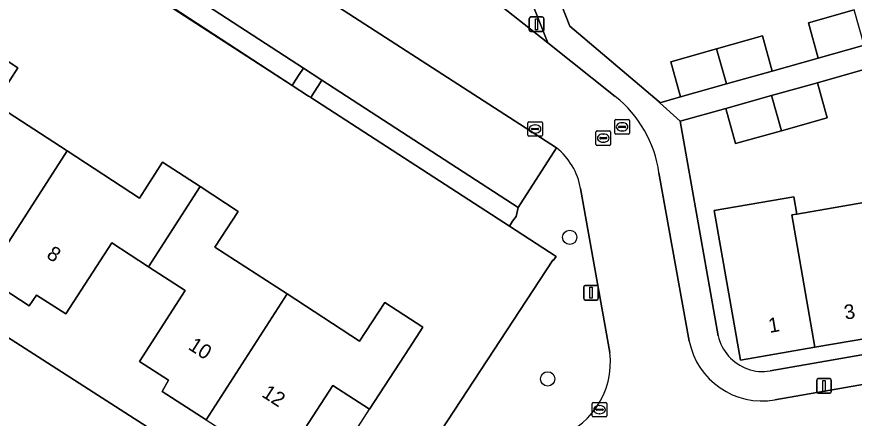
# Model space of a CAD drawing. Extents: x 160157 to 160921, y 381516 to 382045.
# Drawn here: x 160391 to 160448.3, y 381586.3 to 381613.8 of the extents above; entities that cross this region are included whole.
import ezdxf

# ---------------------------------------------------------------- set-up
doc = ezdxf.new("R2010")
doc.units = 0
for name, color, linetype in [('IMGEO_Berm_groen', 7, 'Continuous'), ('IMGEO_Boom', 7, 'Continuous'), ('IMGEO_Erf', 7, 'Continuous'), ('IMGEO_Groenvoorziening', 7, 'Continuous'), ('IMGEO_Haag', 7, 'Continuous'), ('IMGEO_Hek', 7, 'Continuous'), ('IMGEO_Kolk', 7, 'Continuous'), ('IMGEO_Lichtmast', 7, 'Continuous'), ('IMGEO_Muur', 7, 'Continuous'), ('IMGEO_Pand', 7, 'Continuous'), ('IMGEO_Pand_nummerreeks', 7, 'Continuous'), ('IMGEO_Pand_overbouw', 7, 'Continuous'), ('IMGEO_Parkeervlak_open', 7, 'Continuous'), ('IMGEO_Rijbaan_lokaal_open', 7, 'Continuous'), ('IMGEO_Rioolput', 7, 'Continuous'), ('IMGEO_Voetpad_open', 7, 'Continuous')]:
    doc.layers.add(name, color=color, linetype=linetype)

msp = doc.modelspace()

# ---------------------------------------------------------------- linework, layer by layer
at = {"layer": 'IMGEO_Berm_groen'}
msp.add_lwpolyline([(160423.335, 381615.167), (160427.338, 381611.987), (160422.807, 381623.418)], dxfattribs=at)
at = {"layer": 'IMGEO_Boom'}
for centre in [(160428.832, 381598.68), (160427.323, 381588.986)]:
    msp.add_circle(centre, 0.489, dxfattribs=at)
at = {"layer": 'IMGEO_Erf'}
for points in [[(160319.436, 381635.145), (160331.317, 381627.79), (160361.156, 381608.556), (160362.318, 381609.828), (160405.188, 381582.297), (160414.171, 381576.508), (160427.676, 381597.123), (160427.729, 381597.121), (160427.898, 381597.365), (160424.706, 381599.434), (160411.1, 381608.252), (160410.955, 381608.346), (160409.818, 381609.084), (160392.312, 381620.441), (160387.378, 381623.641), (160380.613, 381628.03), (160378.993, 381629.081)], [(160425.558, 381623.211), (160425.011, 381622.871), (160428.842, 381613.142), (160434.955, 381607.95), (160435.012, 381607.897), (160436.424, 381608.295), (160435.754, 381610.698), (160438.887, 381611.582), (160442.019, 381612.466), (160442.69, 381610.06), (160445.85, 381610.95), (160445.18, 381613.358), (160448.313, 381614.243)], [(160388.457, 381611.96), (160391.045, 381610.273), (160389.452, 381607.827), (160394.423, 381604.59), (160399.366, 381601.371), (160400.96, 381603.819), (160403.526, 381602.148), (160406.131, 381600.452), (160404.544, 381598.015), (160409.48, 381594.8), (160414.449, 381591.564), (160416.176, 381594.217), (160418.776, 381592.526), (160417.859, 381591.116), (160415.133, 381586.924), (160412.612, 381588.544), (160410.42, 381585.162)], [(160449.386, 381610.274), (160445.787, 381609.263), (160446.456, 381606.859), (160443.323, 381605.977), (160440.19, 381605.095), (160439.52, 381607.504), (160436.387, 381606.629), (160438.993, 381591.936)], [(160450.722, 381592.036), (160445.619, 381591.148), (160440.515, 381590.26), (160438.723, 381600.521), (160444.179, 381601.45), (160444.381, 381600.268), (160448.976, 381601.06)], [(160403.937, 381586.18), (160400.921, 381588.125), (160401.367, 381588.9), (160399.374, 381590.172), (160402.506, 381595.039), (160399.991, 381596.666), (160397.476, 381598.293), (160394.328, 381593.43), (160392.318, 381594.717), (160391.826, 381593.98), (160388.821, 381595.924)], [(160442.549, 381589.545), (160466.211, 381593.679)]]:
    msp.add_lwpolyline(points, dxfattribs=at)
for centre, radius, start, end in [((160442.05, 381592.631), 3.135, 192.81425, 250.63181), ((160442.01, 381592.362), 2.868, 249.59106, 280.8262)]:
    msp.add_arc(centre, radius, start, end, dxfattribs=at)
at = {"layer": 'IMGEO_Groenvoorziening'}
for points in [[(160400.97, 381616.489), (160393.122, 381621.564), (160392.872, 381621.233), (160392.567, 381620.809), (160392.312, 381620.441), (160409.818, 381609.084), (160410.056, 381609.447), (160410.307, 381609.829), (160410.593, 381610.266), (160404.025, 381614.525)], [(160411.859, 381609.445), (160411.575, 381608.999), (160411.332, 381608.617), (160411.1, 381608.252), (160424.706, 381599.434), (160424.916, 381599.792), (160425.159, 381600.114), (160425.31, 381600.723)]]:
    msp.add_lwpolyline(points, close=True, dxfattribs=at)
for points in [[(160427.931, 381604.811), (160425.31, 381600.723), (160425.159, 381600.114), (160424.916, 381599.792), (160424.706, 381599.434), (160427.898, 381597.365), (160427.729, 381597.121), (160427.676, 381597.123), (160414.171, 381576.508), (160414.766, 381576.125), (160418.106, 381581.208)], [(160431.572, 381590.8), (160429.575, 381602.028)]]:
    msp.add_lwpolyline(points, dxfattribs=at)
for centre, radius, start, end in [((160425.017, 381601.213), 4.63, 10.14305, 51.00015), ((160426.158, 381590.124), 5.456, 284.32458, 7.11479)]:
    msp.add_arc(centre, radius, start, end, dxfattribs=at)
at = {"layer": 'IMGEO_Haag'}
for points in [[(160392.872, 381621.233), (160392.567, 381620.809), (160392.312, 381620.441), (160409.818, 381609.084), (160410.056, 381609.447), (160410.307, 381609.829), (160410.593, 381610.266), (160404.025, 381614.525), (160400.97, 381616.489), (160393.122, 381621.564)], [(160411.859, 381609.445), (160411.575, 381608.999), (160411.332, 381608.617), (160411.1, 381608.252), (160424.706, 381599.434), (160424.916, 381599.792), (160425.159, 381600.114), (160425.31, 381600.723)]]:
    msp.add_lwpolyline(points, close=True, dxfattribs=at)
at = {"layer": 'IMGEO_Hek'}
msp.add_lwpolyline([(160414.171, 381576.508), (160427.676, 381597.123)], dxfattribs=at)
at = {"layer": 'IMGEO_Kolk'}
for p, q in [((160425.956, 381605.67), (160425.956, 381606.522)), ((160426.031, 381606.596), (160426.883, 381606.596)), ((160426.444, 381606.376), (160426.469, 381606.376)), ((160426.957, 381606.522), (160426.957, 381605.67)), ((160426.215, 381606.09), (160426.215, 381606.102)), ((160426.653, 381606.053), (160426.255, 381606.053)), ((160426.258, 381606.139), (160426.656, 381606.139)), ((160426.467, 381605.816), (160426.442, 381605.816)), ((160426.699, 381606.102), (160426.699, 381606.09)), ((160426.883, 381605.596), (160426.031, 381605.596)), ((160430.446, 381587.38), (160431.298, 381587.38)), ((160430.371, 381586.454), (160430.371, 381587.306)), ((160430.63, 381586.874), (160430.63, 381586.886)), ((160431.068, 381586.837), (160430.67, 381586.837)), ((160430.673, 381586.923), (160431.071, 381586.923)), ((160430.859, 381587.16), (160430.884, 381587.16)), ((160431.114, 381586.886), (160431.114, 381586.874)), ((160431.372, 381587.306), (160431.372, 381586.454)), ((160431.298, 381586.38), (160430.446, 381586.38)), ((160430.882, 381586.6), (160430.857, 381586.6))]:
    msp.add_line(p, q, dxfattribs=at)
for points in [[(160425.956, 381605.67), (160425.956, 381606.522)], [(160426.031, 381606.596), (160426.883, 381606.596)], [(160426.957, 381606.522), (160426.957, 381605.67)], [(160426.883, 381605.596), (160426.031, 381605.596)], [(160430.446, 381587.38), (160431.298, 381587.38)], [(160430.371, 381586.454), (160430.371, 381587.306)], [(160431.372, 381587.306), (160431.372, 381586.454)], [(160431.298, 381586.38), (160430.446, 381586.38)]]:
    msp.add_lwpolyline(points, dxfattribs=at)
for centre, radius, start, end in [((160426.033, 381606.52), 0.0765, 91.55205, 178.44795), ((160426.033, 381606.52), 0.0765, 91.55205, 178.44795), ((160426.881, 381606.52), 0.0765, 1.55205, 88.44795), ((160426.881, 381606.52), 0.0765, 1.55205, 88.44795), ((160426.255, 381606.099), 0.0403, 85.87752, 175.75265), ((160426.252, 381606.089), 0.0366, 178.93798, 274.71019), ((160426.656, 381606.096), 0.043, 264.86636, 352.45326), ((160426.66, 381606.101), 0.0386, 1.73085, 96.63898), ((160426.033, 381605.672), 0.0765, 181.55205, 268.44795), ((160426.033, 381605.672), 0.0765, 181.55205, 268.44795), ((160426.881, 381605.672), 0.0765, 271.55205, 358.44795), ((160426.881, 381605.672), 0.0765, 271.55205, 358.44795), ((160430.448, 381587.304), 0.0765, 91.55205, 178.44795), ((160430.448, 381587.304), 0.0765, 91.55205, 178.44795), ((160431.296, 381587.304), 0.0765, 1.55205, 88.44795), ((160431.296, 381587.304), 0.0765, 1.55205, 88.44795), ((160430.67, 381586.883), 0.0403, 85.87752, 175.75265), ((160430.667, 381586.873), 0.0366, 178.93798, 274.71019), ((160431.071, 381586.88), 0.043, 264.86636, 352.45326), ((160431.075, 381586.885), 0.0386, 1.73085, 96.63898), ((160430.448, 381586.456), 0.0765, 181.55205, 268.44795), ((160430.448, 381586.456), 0.0765, 181.55205, 268.44795), ((160431.296, 381586.456), 0.0765, 271.55205, 358.44795), ((160431.296, 381586.456), 0.0765, 271.55205, 358.44795)]:
    msp.add_arc(centre, radius, start, end, dxfattribs=at)
for centre, major_axis, ratio, start_param, end_param in [((160426.443, 381606.096), (-0.387, 0.002), 0.722429, 4.712389, 7.853982), ((160426.468, 381606.096), (-0.39, 0.002), 0.717154, 1.570796, 4.712389), ((160430.858, 381586.88), (-0.387, 0.002), 0.722429, 4.712389, 7.853982), ((160430.883, 381586.88), (-0.39, 0.002), 0.717154, 1.570796, 4.712389)]:
    msp.add_ellipse(centre, major_axis=major_axis, ratio=ratio, start_param=start_param, end_param=end_param, dxfattribs=at)
at = {"layer": 'IMGEO_Lichtmast'}
for p, q in [((160426.165, 381613.769), (160426.955, 381613.769)), ((160426.955, 381613.769), (160426.165, 381613.769)), ((160426.065, 381612.869), (160426.065, 381613.669)), ((160426.065, 381613.669), (160426.065, 381612.869)), ((160427.055, 381613.669), (160427.055, 381612.869)), ((160427.055, 381612.869), (160427.055, 381613.669)), ((160426.955, 381612.769), (160426.165, 381612.769)), ((160426.165, 381612.769), (160426.955, 381612.769)), ((160429.796, 381594.487), (160429.796, 381595.287)), ((160429.796, 381595.287), (160429.796, 381594.487)), ((160429.896, 381595.387), (160430.686, 381595.387)), ((160430.686, 381595.387), (160429.896, 381595.387)), ((160430.786, 381595.287), (160430.786, 381594.487)), ((160430.786, 381594.487), (160430.786, 381595.287)), ((160430.686, 381594.387), (160429.896, 381594.387)), ((160429.896, 381594.387), (160430.686, 381594.387)), ((160445.751, 381588.108), (160445.751, 381588.908)), ((160445.751, 381588.908), (160445.751, 381588.108)), ((160445.851, 381589.008), (160446.641, 381589.008)), ((160446.641, 381589.008), (160445.851, 381589.008)), ((160446.741, 381588.908), (160446.741, 381588.108)), ((160446.741, 381588.108), (160446.741, 381588.908)), ((160446.641, 381588.008), (160445.851, 381588.008)), ((160445.851, 381588.008), (160446.641, 381588.008))]:
    msp.add_line(p, q, dxfattribs=at)
for points in [[(160426.485, 381613.644), (160426.635, 381613.644), (160426.635, 381612.894), (160426.485, 381612.894), (160426.485, 381613.644)], [(160430.216, 381595.262), (160430.366, 381595.262), (160430.366, 381594.512), (160430.216, 381594.512), (160430.216, 381595.262)], [(160446.171, 381588.883), (160446.321, 381588.883), (160446.321, 381588.133), (160446.171, 381588.133), (160446.171, 381588.883)]]:
    msp.add_lwpolyline(points, dxfattribs=at)
for centre, start, end in [((160426.165, 381613.669), 90, 180), ((160426.165, 381613.669), 90, 180), ((160426.955, 381613.669), 0, 90), ((160426.955, 381613.669), 360, 90), ((160426.165, 381612.869), 180, 270), ((160426.165, 381612.869), 180, 270), ((160426.955, 381612.869), 270, 0), ((160426.955, 381612.869), 270, 0), ((160429.896, 381595.287), 90, 180), ((160429.896, 381595.287), 90, 180), ((160430.686, 381595.287), 0, 90), ((160430.686, 381595.287), 360, 90), ((160429.896, 381594.487), 180, 270), ((160429.896, 381594.487), 180, 270), ((160430.686, 381594.487), 270, 0), ((160430.686, 381594.487), 270, 0), ((160445.851, 381588.908), 90, 180), ((160445.851, 381588.908), 90, 180), ((160446.641, 381588.908), 0, 90), ((160446.641, 381588.908), 360, 90), ((160445.851, 381588.108), 180, 270), ((160445.851, 381588.108), 180, 270), ((160446.641, 381588.108), 270, 0), ((160446.641, 381588.108), 270, 0)]:
    msp.add_arc(centre, 0.1, start, end, dxfattribs=at)
at = {"layer": 'IMGEO_Muur'}
for points in [[(160410.955, 381608.346), (160385.879, 381624.702)], [(160427.729, 381597.121), (160427.898, 381597.365), (160410.955, 381608.346)]]:
    msp.add_lwpolyline(points, dxfattribs=at)
at = {"layer": 'IMGEO_Pand'}
for points in [[(160448.313, 381614.243), (160445.18, 381613.358), (160445.85, 381610.95), (160448.984, 381611.833)], [(160442.019, 381612.466), (160438.887, 381611.582), (160439.557, 381609.178), (160442.69, 381610.06)], [(160388.457, 381611.96), (160384.876, 381606.417), (160387.403, 381604.799), (160384.246, 381599.926), (160386.263, 381598.64), (160385.807, 381597.873), (160388.821, 381595.924), (160394.423, 381604.59), (160389.452, 381607.827), (160391.045, 381610.273)], [(160438.887, 381611.582), (160435.754, 381610.698), (160436.424, 381608.295), (160439.557, 381609.178)], [(160445.787, 381609.263), (160442.653, 381608.383), (160443.323, 381605.977), (160446.456, 381606.859)], [(160442.653, 381608.383), (160439.52, 381607.504), (160440.19, 381605.095), (160443.323, 381605.977)], [(160403.526, 381602.148), (160400.96, 381603.819), (160399.366, 381601.371), (160394.423, 381604.59), (160388.821, 381595.924), (160391.826, 381593.98), (160392.318, 381594.717), (160394.328, 381593.43), (160397.476, 381598.293), (160399.991, 381596.666)], [(160403.526, 381602.148), (160399.991, 381596.666), (160402.506, 381595.039), (160399.374, 381590.172), (160401.367, 381588.9), (160400.921, 381588.125), (160403.937, 381586.18), (160409.48, 381594.8), (160404.544, 381598.015), (160406.131, 381600.452)], [(160444.036, 381600.209), (160444.381, 381600.268), (160444.179, 381601.45), (160438.723, 381600.521), (160440.515, 381590.26), (160445.619, 381591.148)], [(160449.141, 381601.088), (160448.976, 381601.06), (160444.381, 381600.268), (160444.036, 381600.209), (160445.619, 381591.148), (160450.722, 381592.036)], [(160403.937, 381586.18), (160406.952, 381584.236), (160407.449, 381584.957), (160409.454, 381583.672), (160410.42, 381585.162), (160412.612, 381588.544), (160415.133, 381586.924), (160417.859, 381591.116), (160418.776, 381592.526), (160416.176, 381594.217), (160414.449, 381591.564), (160409.48, 381594.8)]]:
    msp.add_lwpolyline(points, close=True, dxfattribs=at)
at = {"layer": 'IMGEO_Pand_overbouw'}
msp.add_lwpolyline([(160410.42, 381585.162), (160412.954, 381583.534), (160415.133, 381586.924), (160412.612, 381588.544)], close=True, dxfattribs=at)
at = {"layer": 'IMGEO_Parkeervlak_open'}
msp.add_lwpolyline([(160406.623, 381618.572), (160404.025, 381614.525), (160410.593, 381610.266), (160411.859, 381609.445), (160425.31, 381600.723), (160427.931, 381604.811)], close=True, dxfattribs=at)
at = {"layer": 'IMGEO_Rijbaan_lokaal_open'}
for points in [[(160412.421, 381623.498), (160411.413, 381622.801), (160406.303, 381626.118), (160400.563, 381629.843), (160387.357, 381638.374), (160384.01, 381633.185), (160390.141, 381629.222), (160390.15, 381629.216), (160390.808, 381628.79), (160390.812, 381628.788), (160403.579, 381620.534), (160406.623, 381618.572), (160427.931, 381604.811)], [(160431.953, 381608.322), (160427.338, 381611.987), (160423.335, 381615.167)], [(160437.014, 381591.58), (160434.942, 381603.088)], [(160429.575, 381602.028), (160431.572, 381590.8)], [(160483.304, 381594.619), (160468.514, 381592.021), (160442.874, 381587.548)]]:
    msp.add_lwpolyline(points, dxfattribs=at)
for centre, radius, start, end in [((160426.848, 381601.936), 8.176, 8.09953, 51.35957), ((160425.017, 381601.213), 4.63, 10.14305, 51.00015), ((160442.01, 381592.567), 5.093, 191.17813, 279.76168), ((160426.158, 381590.124), 5.456, 284.32458, 7.11479)]:
    msp.add_arc(centre, radius, start, end, dxfattribs=at)
at = {"layer": 'IMGEO_Rioolput'}
for p, q in [((160431.919, 381605.816), (160431.919, 381606.668)), ((160431.994, 381606.742), (160432.846, 381606.742)), ((160432.407, 381606.522), (160432.432, 381606.522)), ((160432.92, 381606.668), (160432.92, 381605.816)), ((160430.63, 381605.045), (160430.63, 381605.897)), ((160430.705, 381605.971), (160431.557, 381605.971)), ((160431.118, 381605.751), (160431.143, 381605.751)), ((160431.631, 381605.897), (160431.631, 381605.045)), ((160432.846, 381605.742), (160431.994, 381605.742)), ((160432.178, 381606.236), (160432.178, 381606.248)), ((160432.616, 381606.199), (160432.218, 381606.199)), ((160432.221, 381606.285), (160432.619, 381606.285)), ((160432.43, 381605.962), (160432.405, 381605.962)), ((160432.662, 381606.248), (160432.662, 381606.236)), ((160430.889, 381605.465), (160430.889, 381605.477)), ((160431.327, 381605.428), (160430.929, 381605.428)), ((160430.932, 381605.514), (160431.33, 381605.514)), ((160431.141, 381605.191), (160431.116, 381605.191)), ((160431.373, 381605.477), (160431.373, 381605.465)), ((160431.557, 381604.971), (160430.705, 381604.971))]:
    msp.add_line(p, q, dxfattribs=at)
for points in [[(160431.919, 381605.816), (160431.919, 381606.668)], [(160431.994, 381606.742), (160432.846, 381606.742)], [(160432.92, 381606.668), (160432.92, 381605.816)], [(160430.63, 381605.045), (160430.63, 381605.897)], [(160430.705, 381605.971), (160431.557, 381605.971)], [(160431.631, 381605.897), (160431.631, 381605.045)], [(160432.846, 381605.742), (160431.994, 381605.742)], [(160431.557, 381604.971), (160430.705, 381604.971)]]:
    msp.add_lwpolyline(points, dxfattribs=at)
for centre, radius, start, end in [((160431.996, 381606.666), 0.0765, 91.55205, 178.44795), ((160431.996, 381606.666), 0.0765, 91.55205, 178.44795), ((160432.844, 381606.666), 0.0765, 1.55205, 88.44795), ((160432.844, 381606.666), 0.0765, 1.55205, 88.44795), ((160430.707, 381605.895), 0.0765, 91.55205, 178.44795), ((160430.707, 381605.895), 0.0765, 91.55205, 178.44795), ((160431.555, 381605.895), 0.0765, 1.55205, 88.44795), ((160431.555, 381605.895), 0.0765, 1.55205, 88.44795), ((160431.996, 381605.818), 0.0765, 181.55205, 268.44795), ((160431.996, 381605.818), 0.0765, 181.55205, 268.44795), ((160432.218, 381606.245), 0.0403, 85.87752, 175.75265), ((160432.215, 381606.235), 0.0366, 178.93798, 274.71019), ((160432.619, 381606.242), 0.043, 264.86636, 352.45326), ((160432.623, 381606.247), 0.0386, 1.73085, 96.63898), ((160432.844, 381605.818), 0.0765, 271.55205, 358.44795), ((160432.844, 381605.818), 0.0765, 271.55205, 358.44795), ((160430.929, 381605.474), 0.0403, 85.87752, 175.75265), ((160430.926, 381605.464), 0.0366, 178.93798, 274.71019), ((160431.33, 381605.471), 0.043, 264.86636, 352.45326), ((160431.334, 381605.476), 0.0386, 1.73085, 96.63898), ((160430.707, 381605.047), 0.0765, 181.55205, 268.44795), ((160430.707, 381605.047), 0.0765, 181.55205, 268.44795), ((160431.555, 381605.047), 0.0765, 271.55205, 358.44795), ((160431.555, 381605.047), 0.0765, 271.55205, 358.44795)]:
    msp.add_arc(centre, radius, start, end, dxfattribs=at)
for centre, major_axis, ratio, start_param, end_param in [((160432.406, 381606.242), (-0.387, 0.002), 0.722429, 4.712389, 7.853982), ((160432.431, 381606.242), (-0.39, 0.002), 0.717154, 1.570796, 4.712389), ((160431.117, 381605.471), (-0.387, 0.002), 0.722429, 4.712389, 7.853982), ((160431.142, 381605.471), (-0.39, 0.002), 0.717154, 1.570796, 4.712389)]:
    msp.add_ellipse(centre, major_axis=major_axis, ratio=ratio, start_param=start_param, end_param=end_param, dxfattribs=at)
at = {"layer": 'IMGEO_Voetpad_open'}
for points in [[(160422.807, 381623.418), (160427.338, 381611.987), (160431.953, 381608.322)], [(160438.993, 381591.936), (160436.387, 381606.629), (160435.012, 381607.897), (160434.955, 381607.95), (160428.842, 381613.142), (160425.011, 381622.871), (160425.558, 381623.211)], [(160422.355, 381570.648), (160420.44, 381572.267), (160419.369, 381573.18), (160414.766, 381576.125), (160414.171, 381576.508), (160405.188, 381582.297), (160362.318, 381609.828)], [(160434.942, 381603.088), (160437.014, 381591.58)], [(160482.924, 381596.599), (160467.769, 381593.951), (160466.899, 381593.799), (160466.211, 381593.679), (160442.549, 381589.545)], [(160442.874, 381587.548), (160468.514, 381592.021), (160483.304, 381594.619)]]:
    msp.add_lwpolyline(points, dxfattribs=at)
for points in [[(160457.496, 381612.549), (160460.663, 381613.44), (160462.891, 381613.471), (160462.692, 381614.629), (160462.545, 381615.463), (160462.019, 381615.37), (160458.869, 381614.55), (160455.719, 381613.73), (160452.117, 381612.715), (160448.984, 381611.833), (160445.85, 381610.95), (160442.69, 381610.06), (160439.557, 381609.178), (160436.424, 381608.295), (160435.012, 381607.897), (160436.387, 381606.629), (160439.52, 381607.504), (160442.653, 381608.383), (160445.787, 381609.263), (160449.386, 381610.274), (160452.521, 381611.153), (160455.655, 381612.032)], [(160410.593, 381610.266), (160410.307, 381609.829), (160410.056, 381609.447), (160409.818, 381609.084), (160410.955, 381608.346), (160411.1, 381608.252), (160411.332, 381608.617), (160411.575, 381608.999), (160411.859, 381609.445)]]:
    msp.add_lwpolyline(points, close=True, dxfattribs=at)
for centre, radius, start, end in [((160426.848, 381601.936), 8.176, 8.09953, 51.35957), ((160442.01, 381592.567), 5.093, 191.17813, 279.76168), ((160442.05, 381592.631), 3.135, 192.81425, 250.63181), ((160442.01, 381592.362), 2.868, 249.59106, 280.8262)]:
    msp.add_arc(centre, radius, start, end, dxfattribs=at)

# ---------------------------------------------------------------- texts
at = {"layer": 'IMGEO_Pand_nummerreeks'}
for s, rotation, p in [('8', 327.20564, (160392.944, 381597.32)), ('3', 9.87206, (160447.704, 381593.033)), ('1', 9.87206, (160442.521, 381592.131)), ('10', 327.18441, (160402.645, 381591.062)), ('12', 327.18441, (160407.68, 381587.815))]:
    msp.add_text(s, height=1, rotation=rotation, dxfattribs=at).set_placement(p)

doc.saveas('drawing.dxf')
